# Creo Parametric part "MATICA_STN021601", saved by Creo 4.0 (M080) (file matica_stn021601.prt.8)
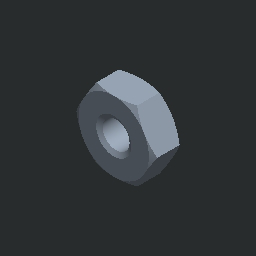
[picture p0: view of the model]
Units: millimeter Kilogram Sec (mmKs); MM, KILOGRAM, SECS
Materials in the file: OCEL_N

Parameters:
  MFG_WP_MATERIAL = "OCEL"
  NAZOV = "MATICA_STN021601"
  NORMA = "STN 02 1601"
  PTC_MATERIAL_NAME = "OCEL_N"

Other parameters: HMOTNOST, HUSTOTA, D12, D19

Created from: C021601.PRT

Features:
  1. datum plane "DTM1"
  2. cut
  3. cut
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
Other named items: THRU

Layers: 1, 2, 3, 4, 5, 6, 7, 8, 9, 10, 11, 12, 13, 14, 15, 16, 17, 18, 19, 20, 21, 22, 23, 24, 25, 26, 27, 28, 29, 30, 31, 32

Family table entries: GENERIC, MATICA_M5, MATICA_STN021601, value(d_val), 2/ , value(i_val), MATICA_M6, MATICA_STN021601, 2/$, MATICA_M8, MATICA_STN021601, !/ , 2/*, MATICA_M10, MATICA_STN021601, !/$, 2/ , 2/0, MATICA_M12, MATICA_STN021601, !/(, 2/$, 2/2, MATICA_M14, MATICA_STN021601, !/,, 2/&, 2/5, MATICA_M16, MATICA_STN021601, !/0, 2/*, 2/8, MATICA_M18, MATICA_STN021601, !/2, 2/., 2/;, MATICA_M20, MATICA_STN021601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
